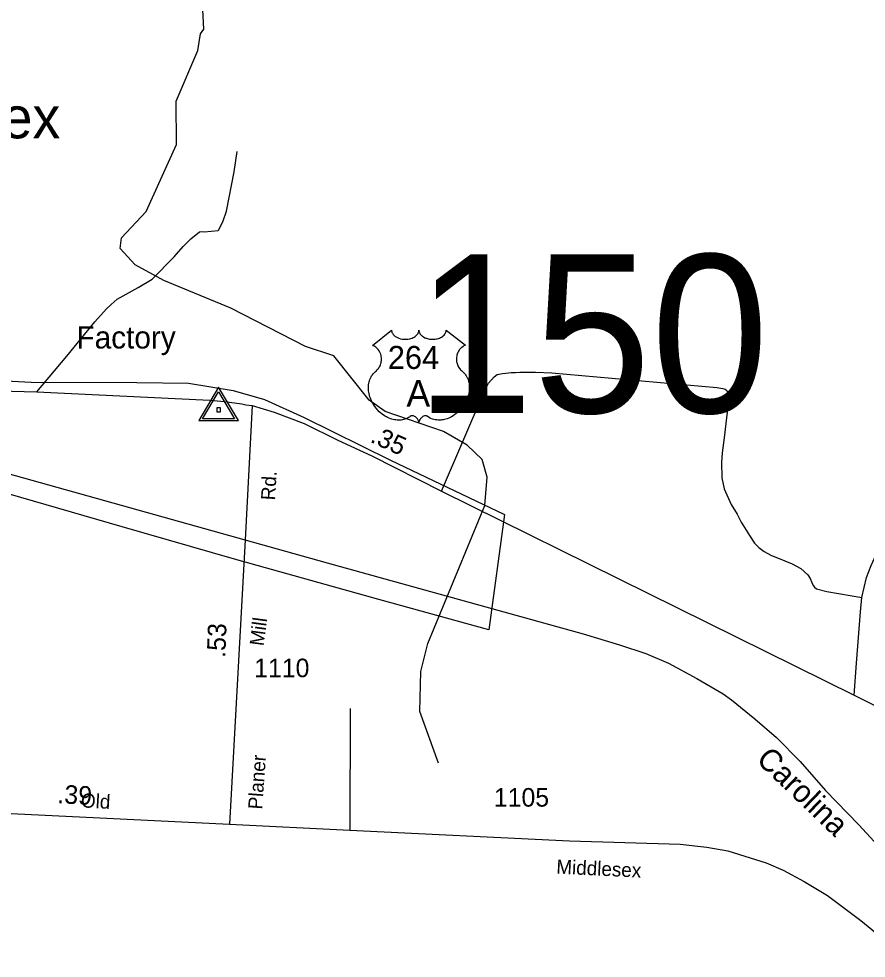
# Model space of a CAD drawing. Extents: x 2220236 to 2384410, y 720751 to 894131.
# Drawn here: x 2239837 to 2245544, y 738736 to 745063 of the extents above; entities that cross this region are included whole.
import ezdxf

# ---------------------------------------------------------------- set-up
doc = ezdxf.new("R2010")
doc.units = 0
for name, color, linetype in [('Exist Boundary Political City Limit New', 7, 'Continuous'), ('Exist Civil Demographics City Label', 7, 'Continuous'), ('Exist Hydrographic Misc Water Feature', 7, 'Continuous'), ('Exist Railroad Mainline', 7, 'Continuous'), ('Exist Railroad Mainline Label', 7, 'Continuous'), ('Exist Road Non-System Type 51', 7, 'Continuous'), ('Exist Road Primary US Attributed', 7, 'Continuous'), ('Exist Road Primary US Mileage Hundredths English Label', 7, 'Continuous'), ('Exist Road Primary US Shield CELL', 7, 'Continuous'), ('Exist Road Primary US Shield Number Label', 7, 'Continuous'), ('Exist Road Secondary Mileage Hundredths English Label', 7, 'Continuous'), ('Exist Road Secondary Structure Standard Bridge Number Label', 7, 'Continuous'), ('Exist Road Secondary Type 51 Attributed', 7, 'Continuous'), ('Exist Road Secondary Type 51 Label', 7, 'Continuous'), ('Exist Road Secondary Type 51 Number Label', 7, 'Continuous'), ('Exist Survey Geodetic Marker CELL', 7, 'Continuous'), ('Exist Survey Geodetic Marker Label', 7, 'Continuous'), ('Map Preparation Boundary City Limit Buffer Line', 7, 'Continuous')]:
    doc.layers.add(name, color=color, linetype=linetype)

msp = doc.modelspace()

# ---------------------------------------------------------------- linework, layer by layer
at = {"layer": 'Exist Boundary Political City Limit New'}
msp.add_lwpolyline([(2239358.5, 742644.2), (2239919.8, 742614.7), (2240632, 742612.2), (2240978.8, 742607.9), (2241281.8, 742559.4), (2241492, 742498.8), (2241758.8, 742377.7), (2242340.5, 742090.9), (2243108.2, 741723.4), (2243003.2, 740948.1), (2242262, 741152.1), (2241290.5, 741423.7), (2240532.8, 741640.4), (2239081, 742060)], dxfattribs=at)
at = {"layer": 'Exist Hydrographic Misc Water Feature'}
msp.add_lwpolyline([(2242664.7, 740050.2), (2242537.8, 740397.2), (2242543.7, 740666), (2242591.7, 740855.2), (2242975.8, 741785.5), (2242990.7, 741975.4), (2242956.7, 742094.1), (2242855.8, 742191.3), (2242696.7, 742283.2), (2242304.6, 742419.1), (2242195.8, 742493.6), (2241959.7, 742793.6), (2241767.8, 742856.6), (2241265.6, 743112.9), (2240814.7, 743299.3), (2240621.8, 743404.9), (2240520.7, 743515.2), (2240528.7, 743587.2), (2240693.7, 743764.2), (2240898.8, 744216), (2240896.7, 744507.9), (2241043.8, 744849.3), (2241059.8, 744960.5), (2241083.8, 744992.8), (2241073.7, 745166.8)], dxfattribs=at)
at = {"layer": 'Exist Railroad Mainline'}
msp.add_lwpolyline([(2239641.8, 742035), (2241914, 741399.8), (2243637.2, 740920.1), (2243883.6, 740846), (2244060, 740787.6), (2244212.4, 740722.9), (2244403.2, 740620.4), (2244580.1, 740516), (2244636.2, 740476.5), (2244793.3, 740347.7), (2244940.1, 740222.9), (2245099.5, 740060.2), (2245270.9, 739865.8), (2245494.9, 739633.8), (2245650, 739467.1)], dxfattribs=at)
at = {"layer": 'Exist Road Non-System Type 51'}
msp.add_line((2242068.4, 740418), (2242067.1, 739599.2), dxfattribs=at)
for points in [[(2239957.5, 742549.4), (2240161.4, 742790.9), (2240349.5, 743022.4), (2240426.7, 743109), (2240458.5, 743139.3), (2240500.2, 743173.6), (2240641.4, 743252.7), (2240734.9, 743309.4), (2240883.8, 743458.5), (2240945, 743529), (2240996.7, 743581.3), (2241054.2, 743627.9), (2241066.3, 743629.9), (2241086.2, 743628.1), (2241179.4, 743636.2), (2241182, 743638.9), (2241211.6, 743695.1), (2241235, 743767.4), (2241286.9, 744031.6), (2241307.7, 744167.8)], [(2242683.7, 741881.9), (2242970.1, 742550), (2242999.7, 742608.2), (2243039.2, 742652.3), (2243059.1, 742666.5), (2243095.1, 742674.8), (2243117.1, 742675.1), (2243153, 742681.4), (2243183, 742681.6), (2243211, 742683.8), (2243317, 742682.6), (2243426.8, 742677.6), (2244539.1, 742580.7), (2244579.2, 742573.1), (2244593.3, 742569.2), (2244605.3, 742559.2), (2244613.5, 742539.4), (2244617.7, 742521.3), (2244618, 742485.3), (2244614.1, 742471.4), (2244587.9, 742241.2), (2244574.8, 742139.1), (2244569.3, 742075.2), (2244572.2, 741971.2), (2244588.7, 741897.5), (2244635.7, 741791.7), (2244674.1, 741726.2), (2244702.6, 741672.4), (2244757.2, 741582.9), (2244791.7, 741531.2), (2244821.9, 741501.4), (2244856.1, 741475.7), (2244902.2, 741450.1), (2244996.6, 741413), (2245046.7, 741391.4), (2245104.9, 741361.8), (2245151.2, 741318.3), (2245167.5, 741292.3), (2245177.5, 741266.5), (2245187.7, 741246.5), (2245195.9, 741234.6), (2245210, 741222.7), (2245280, 741205.2), (2245514.4, 741165.2)], [(2245514.4, 741165.2), (2245547.1, 741299.5), (2245576.6, 741381.7), (2245623.6, 741479.9), (2245651.3, 741516.1), (2245661.3, 741526.3), (2245709.3, 741532.7), (2245753.3, 741527), (2245779.2, 741521.3), (2245819.4, 741509.7)], [(2245463.6, 740507), (2245477.9, 740723.1), (2245505, 741069.2), (2245514.4, 741165.2)]]:
    msp.add_lwpolyline(points, dxfattribs=at)
at = {"layer": 'Exist Road Primary US Attributed'}
for points in [[(2236089.7, 743291.6), (2236461.6, 743208.7), (2236818.3, 743109.6), (2237181, 743012.5), (2237585.7, 742897.8), (2237952.5, 742792.9), (2238049, 742766.7), (2238252.9, 742711.4), (2238411.3, 742664.7), (2238595.6, 742620.3), (2238695.7, 742601.1), (2238779.6, 742587.8), (2238857.8, 742578.4), (2238943.7, 742575.2), (2239015.7, 742575.7), (2239197.6, 742571.2), (2239957.5, 742549.4), (2241123.5, 742495), (2241221.5, 742485.8), (2241339.5, 742468.7), (2241365.6, 742462.8), (2241409.7, 742459.3)], [(2241409.7, 742459.3), (2241555.9, 742414.5), (2241758.5, 742336.2), (2241985.3, 742224.1), (2242214.1, 742119.9), (2242683.7, 741881.9), (2245463.6, 740507), (2245943.4, 740267), (2246389.2, 740038.9), (2246724.3, 739863.7), (2246953.1, 739759.6), (2247223.7, 739667.8), (2247470, 739627.8), (2247814, 739604.5), (2248421.9, 739577.6), (2249328.8, 739522.4)]]:
    msp.add_lwpolyline(points, dxfattribs=at)
at = {"layer": 'Exist Road Primary US Shield CELL'}
msp.add_lwpolyline([(2242347.7, 742965.8), (2242348.1, 742960.5), (2242349.4, 742954.2), (2242350.3, 742950.9), (2242353.3, 742944.7), (2242358.2, 742937.3), (2242365, 742930.1), (2242372.6, 742923.8), (2242377.8, 742920.4), (2242386.6, 742915.7), (2242396.5, 742911.6), (2242407.6, 742908.4), (2242418.9, 742906.1), (2242431.3, 742904.7), (2242443.5, 742904.5), (2242456.7, 742905.5), (2242471.3, 742908.3), (2242478.1, 742910), (2242485.6, 742912.6), (2242492.6, 742915.5), (2242500.3, 742919.6), (2242506.4, 742923.6), (2242511.2, 742927.1), (2242518.1, 742933.6), (2242523.5, 742940.4), (2242525.8, 742944.2), (2242527.8, 742947.8), (2242530.5, 742955.6), (2242531.2, 742959), (2242531.8, 742966.1), (2242532.2, 742960.1), (2242532.8, 742956.4), (2242533.8, 742952.7), (2242535.3, 742948.9), (2242538, 742943.4), (2242541.1, 742938.8), (2242546.8, 742932.1), (2242550.4, 742928.7), (2242553.7, 742926.1), (2242562.4, 742920.1), (2242572.6, 742914.9), (2242577.6, 742912.7), (2242582.8, 742910.9), (2242589.3, 742908.9), (2242596.1, 742907.3), (2242602.8, 742906.2), (2242609.6, 742905.2), (2242616.6, 742904.6), (2242622.3, 742904.5), (2242629.3, 742904.6), (2242635.7, 742904.9), (2242642.3, 742905.7), (2242649.6, 742906.9), (2242655.5, 742908.2), (2242663.2, 742910.3), (2242670.2, 742912.8), (2242676.4, 742915.4), (2242684.3, 742919.6), (2242690.8, 742923.6), (2242695.5, 742927.4), (2242701.1, 742932.6), (2242706.4, 742938.8), (2242709.5, 742943.2), (2242711.7, 742947.9), (2242713.8, 742952.7), (2242715, 742957.9), (2242715.7, 742962.4), (2242715.8, 742966.2), (2242844.4, 742863.8), (2242841.3, 742862.6), (2242834.4, 742859.2), (2242828.8, 742855.9), (2242820, 742849.7), (2242816.2, 742846.3), (2242812.4, 742842.7), (2242808.9, 742838.9), (2242805.8, 742835.3), (2242802.1, 742830.2), (2242798.7, 742825), (2242795.5, 742819.3), (2242793.1, 742814.4), (2242789.1, 742804), (2242787.2, 742797.5), (2242786, 742791.9), (2242784.5, 742780.5), (2242784.1, 742775), (2242784.1, 742769.6), (2242784.4, 742763.9), (2242785, 742758.4), (2242785.9, 742752.7), (2242786.9, 742747.7), (2242788.4, 742741.6), (2242790.7, 742734.4), (2242793.5, 742727.5), (2242799.4, 742716.3), (2242807, 742704.9), (2242812.4, 742698.6), (2242817.7, 742693.1), (2242825.6, 742686.4), (2242829.9, 742682.6), (2242834.9, 742677.7), (2242842.9, 742668.3), (2242846.2, 742663.9), (2242849.5, 742659), (2242852.5, 742653.9), (2242855.5, 742648.4), (2242858, 742643.6), (2242862.5, 742632.6), (2242865.8, 742621.9), (2242867.3, 742616.3), (2242869.7, 742603.7), (2242870.6, 742597.4), (2242871.6, 742585.1), (2242871.6, 742570.2), (2242870.5, 742556.1), (2242867.8, 742539.6), (2242865.6, 742529.7), (2242862.3, 742518.2), (2242859, 742508.3), (2242853.1, 742493.6), (2242847.9, 742483), (2242841.2, 742470.5), (2242836.5, 742463), (2242831.1, 742454.9), (2242824.4, 742445.7), (2242816.5, 742435.8), (2242807, 742425.4), (2242799.3, 742417.7), (2242789.3, 742408.7), (2242783.2, 742403.7), (2242774.5, 742397.2), (2242762.7, 742389.3), (2242751, 742382.5), (2242741.1, 742377.4), (2242732.2, 742373.6), (2242720.9, 742369.3), (2242701.9, 742364.1), (2242695, 742362.6), (2242686.8, 742361.4), (2242679.1, 742360.6), (2242671.6, 742360.2), (2242661.6, 742360.2), (2242651.7, 742361), (2242642.3, 742362.3), (2242632.5, 742364.4), (2242622.2, 742367.4), (2242612.9, 742371.1), (2242603.5, 742375.7), (2242587.6, 742385.7), (2242583, 742388.2), (2242580.4, 742388.8), (2242574.2, 742389.1), (2242568.5, 742387.9), (2242562.5, 742385.6), (2242559, 742383.7), (2242554.2, 742380.6), (2242550.6, 742377.7), (2242546.2, 742373.5), (2242543.1, 742370), (2242540.8, 742367.3), (2242536.3, 742360.2), (2242534.7, 742356.8), (2242533.1, 742352.5), (2242531.6, 742346.1), (2242529.6, 742354.2), (2242527.2, 742359.5), (2242524.5, 742364.1), (2242521.6, 742368.1), (2242517.2, 742373.3), (2242513.1, 742377.1), (2242508.3, 742381.1), (2242503.1, 742384.2), (2242499, 742386.3), (2242495.2, 742387.8), (2242490.5, 742388.9), (2242486.7, 742389.2), (2242483.6, 742389.1), (2242479.4, 742388.2), (2242473.5, 742384), (2242468, 742380.2), (2242462, 742376.5), (2242454.9, 742372.7), (2242449.6, 742370.2), (2242443.4, 742367.8), (2242436.1, 742365.4), (2242428.2, 742363.3), (2242420.1, 742361.7), (2242413, 742360.6), (2242405.3, 742359.9), (2242398.4, 742359.7), (2242391.2, 742359.7), (2242384.4, 742360.3), (2242376.6, 742361), (2242366.9, 742362.4), (2242358.8, 742364.2), (2242350.3, 742366.5), (2242341.6, 742369.2), (2242332.2, 742372.8), (2242320.5, 742377.9), (2242312.4, 742382.1), (2242299.6, 742389.4), (2242284.5, 742399.9), (2242273.2, 742409), (2242264.9, 742416.6), (2242252.6, 742429), (2242245.5, 742437.2), (2242234.2, 742451.8), (2242227, 742462.3), (2242222.3, 742470.1), (2242215.5, 742482.5), (2242211.7, 742490.4), (2242206.8, 742501.8), (2242203, 742512.2), (2242199.8, 742522), (2242198.1, 742528.3), (2242195.7, 742539.4), (2242194.2, 742547.2), (2242192.8, 742557.9), (2242192, 742569.2), (2242191.8, 742579.6), (2242192.1, 742588.3), (2242193.1, 742598.4), (2242194.8, 742609.1), (2242196.8, 742618.3), (2242198.7, 742624.9), (2242201.4, 742633), (2242205, 742641.9), (2242209.3, 742650.4), (2242213.3, 742657.5), (2242218.4, 742665), (2242223.4, 742671.5), (2242230, 742678.6), (2242236.8, 742685.2), (2242243.1, 742690.3), (2242250.6, 742697.6), (2242254.4, 742702), (2242259.1, 742708.1), (2242262.8, 742713.8), (2242265.8, 742718.9), (2242269.7, 742726.4), (2242272.1, 742732.1), (2242275, 742740.7), (2242276.5, 742746.8), (2242278, 742754.6), (2242279, 742762), (2242279.4, 742771.2), (2242279.2, 742778.8), (2242278.2, 742787.7), (2242276.5, 742796.2), (2242274.5, 742803.6), (2242271.3, 742812.2), (2242268.4, 742818.4), (2242263.4, 742826.8), (2242258, 742834.7), (2242252.3, 742841), (2242246.6, 742846.7), (2242241.1, 742851), (2242235.9, 742854.7), (2242229.4, 742858.7), (2242223.1, 742861.8), (2242219.1, 742863.4)], close=True, dxfattribs=at)
at = {"layer": 'Exist Road Secondary Type 51 Attributed'}
for p, q in [((2241409.7, 742459.3), (2241360.6, 741554.5)), ((2241360.6, 741554.5), (2241256.6, 739638)), ((2239203.1, 739739.1), (2241256.6, 739638))]:
    msp.add_line(p, q, dxfattribs=at)
msp.add_lwpolyline([(2241256.6, 739638), (2242067.1, 739599.2), (2243547, 739526.6), (2244291.5, 739503.3), (2244470.2, 739485.2), (2244612.6, 739459.3), (2244762.8, 739412.6), (2244871.6, 739378.9), (2244985.5, 739329.7), (2245125.3, 739252), (2245283.3, 739158.7), (2245507.3, 738990.3), (2245818, 738736.3)], dxfattribs=at)
at = {"layer": 'Exist Survey Geodetic Marker CELL'}
for points in [[(2241316.2, 742356.8), (2241182.2, 742582.8), (2241048.8, 742356.8)], [(2241290.3, 742368.9), (2241074.7, 742368.9), (2241182.2, 742551)], [(2241194.5, 742415.5), (2241194.5, 742443.7), (2241170.3, 742443.7), (2241170.3, 742415.5)]]:
    msp.add_lwpolyline(points, close=True, dxfattribs=at)
at = {"layer": 'Map Preparation Boundary City Limit Buffer Line'}
msp.add_lwpolyline([(2239358.5, 742644.2), (2239919.8, 742614.7), (2240632, 742612.2), (2240978.8, 742607.9), (2241281.8, 742559.4), (2241492, 742498.8), (2241758.8, 742377.7), (2242340.5, 742090.9), (2243108.2, 741723.4), (2243003.2, 740948.1), (2242262, 741152.1), (2241290.5, 741423.7), (2240532.8, 741640.4), (2239081, 742060)], dxfattribs=at)

# ---------------------------------------------------------------- texts
at = {"layer": 'Exist Civil Demographics City Label'}
msp.add_text('Middlesex', height=280, dxfattribs=at).set_placement((2238430.8, 744257.5))
at = {"layer": 'Exist Railroad Mainline Label'}
msp.add_text('Carolina', height=150, rotation=316.09727, dxfattribs=at).set_placement((2244796.7, 740065.5))
at = {"layer": 'Exist Road Primary US Mileage Hundredths English Label'}
msp.add_text('.35', height=125, rotation=335.49764, dxfattribs=at).set_placement((2242197.4, 742214.7))
at = {"layer": 'Exist Road Primary US Shield Number Label'}
for s, height, p in [('264', 155, (2242322.1, 742704.5)), ('A', 180, (2242447.3, 742449.6))]:
    msp.add_text(s, height=height, dxfattribs=at).set_placement(p)
at = {"layer": 'Exist Road Secondary Mileage Hundredths English Label'}
for s, rotation, p in [('.53', 87.87826, (2241227.7, 740757.9)), ('.39', 356.68451, (2240094.5, 739781.1))]:
    msp.add_text(s, height=125, rotation=rotation, dxfattribs=at).set_placement(p)
at = {"layer": 'Exist Road Secondary Structure Standard Bridge Number Label'}
msp.add_text('150', height=1066.27, dxfattribs=at).set_placement((2242508.8, 742409))
at = {"layer": 'Exist Road Secondary Type 51 Label'}
for s, rotation, p in [('Rd.', 86.77452, (2241562.8, 741818.2)), ('Mill', 82.36012, (2241485.1, 740835.3)), ('Planer', 85.80392, (2241475.7, 739735.9)), ('Old', 356.68451, (2240253.6, 739752.8)), ('Middlesex', 357.25341, (2243455.6, 739306.3))]:
    msp.add_text(s, height=95, rotation=rotation, dxfattribs=at).set_placement(p)
at = {"layer": 'Exist Road Secondary Type 51 Number Label'}
for s, p in [('1110', (2241422.3, 740628.6)), ('1105', (2243036.7, 739757.1))]:
    msp.add_text(s, height=125, dxfattribs=at).set_placement(p)
at = {"layer": 'Exist Survey Geodetic Marker Label'}
msp.add_text('Factory', height=150, dxfattribs=at).set_placement((2240225.1, 742842.1))

doc.saveas('drawing.dxf')
